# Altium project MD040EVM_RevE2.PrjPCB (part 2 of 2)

## Sheet MD040_ezFET_RevE2.SchDoc
size 431 x 279 mm; Date: Not shown in title block; ApprovedBy: Not shown in title block; CheckedBy: Not shown in title block; Author: Not shown in title block; CompanyName: Not shown in title block; Engineer: Not shown in title block; Organization: Not shown in title block; Address1: Not shown in title block; Address2: Not shown in title block; Address3: Not shown in title block; Address4: Not shown in title block; DocumentNumber: 2; Revision: Use project parameter SCH_Rev; SheetNumber: 2; SheetTotal: 3; PageSetup: Record=PageOptions¦CenterHorizontal=True¦CenterVertical=True¦PrintScale=1.00¦XCorrection=1.00¦YCorrection=1.00¦PrintKind=0¦BorderSize=5000000¦LeftOffset=0¦BottomOffset=0¦Orientation=2¦PaperLength=1000¦PaperWidth=1000¦Scale=100¦PaperSource=15¦PrintQuality=600¦MediaType=1¦DitherType=10¦PaperKind=Letter¦PrintScaleMode=1
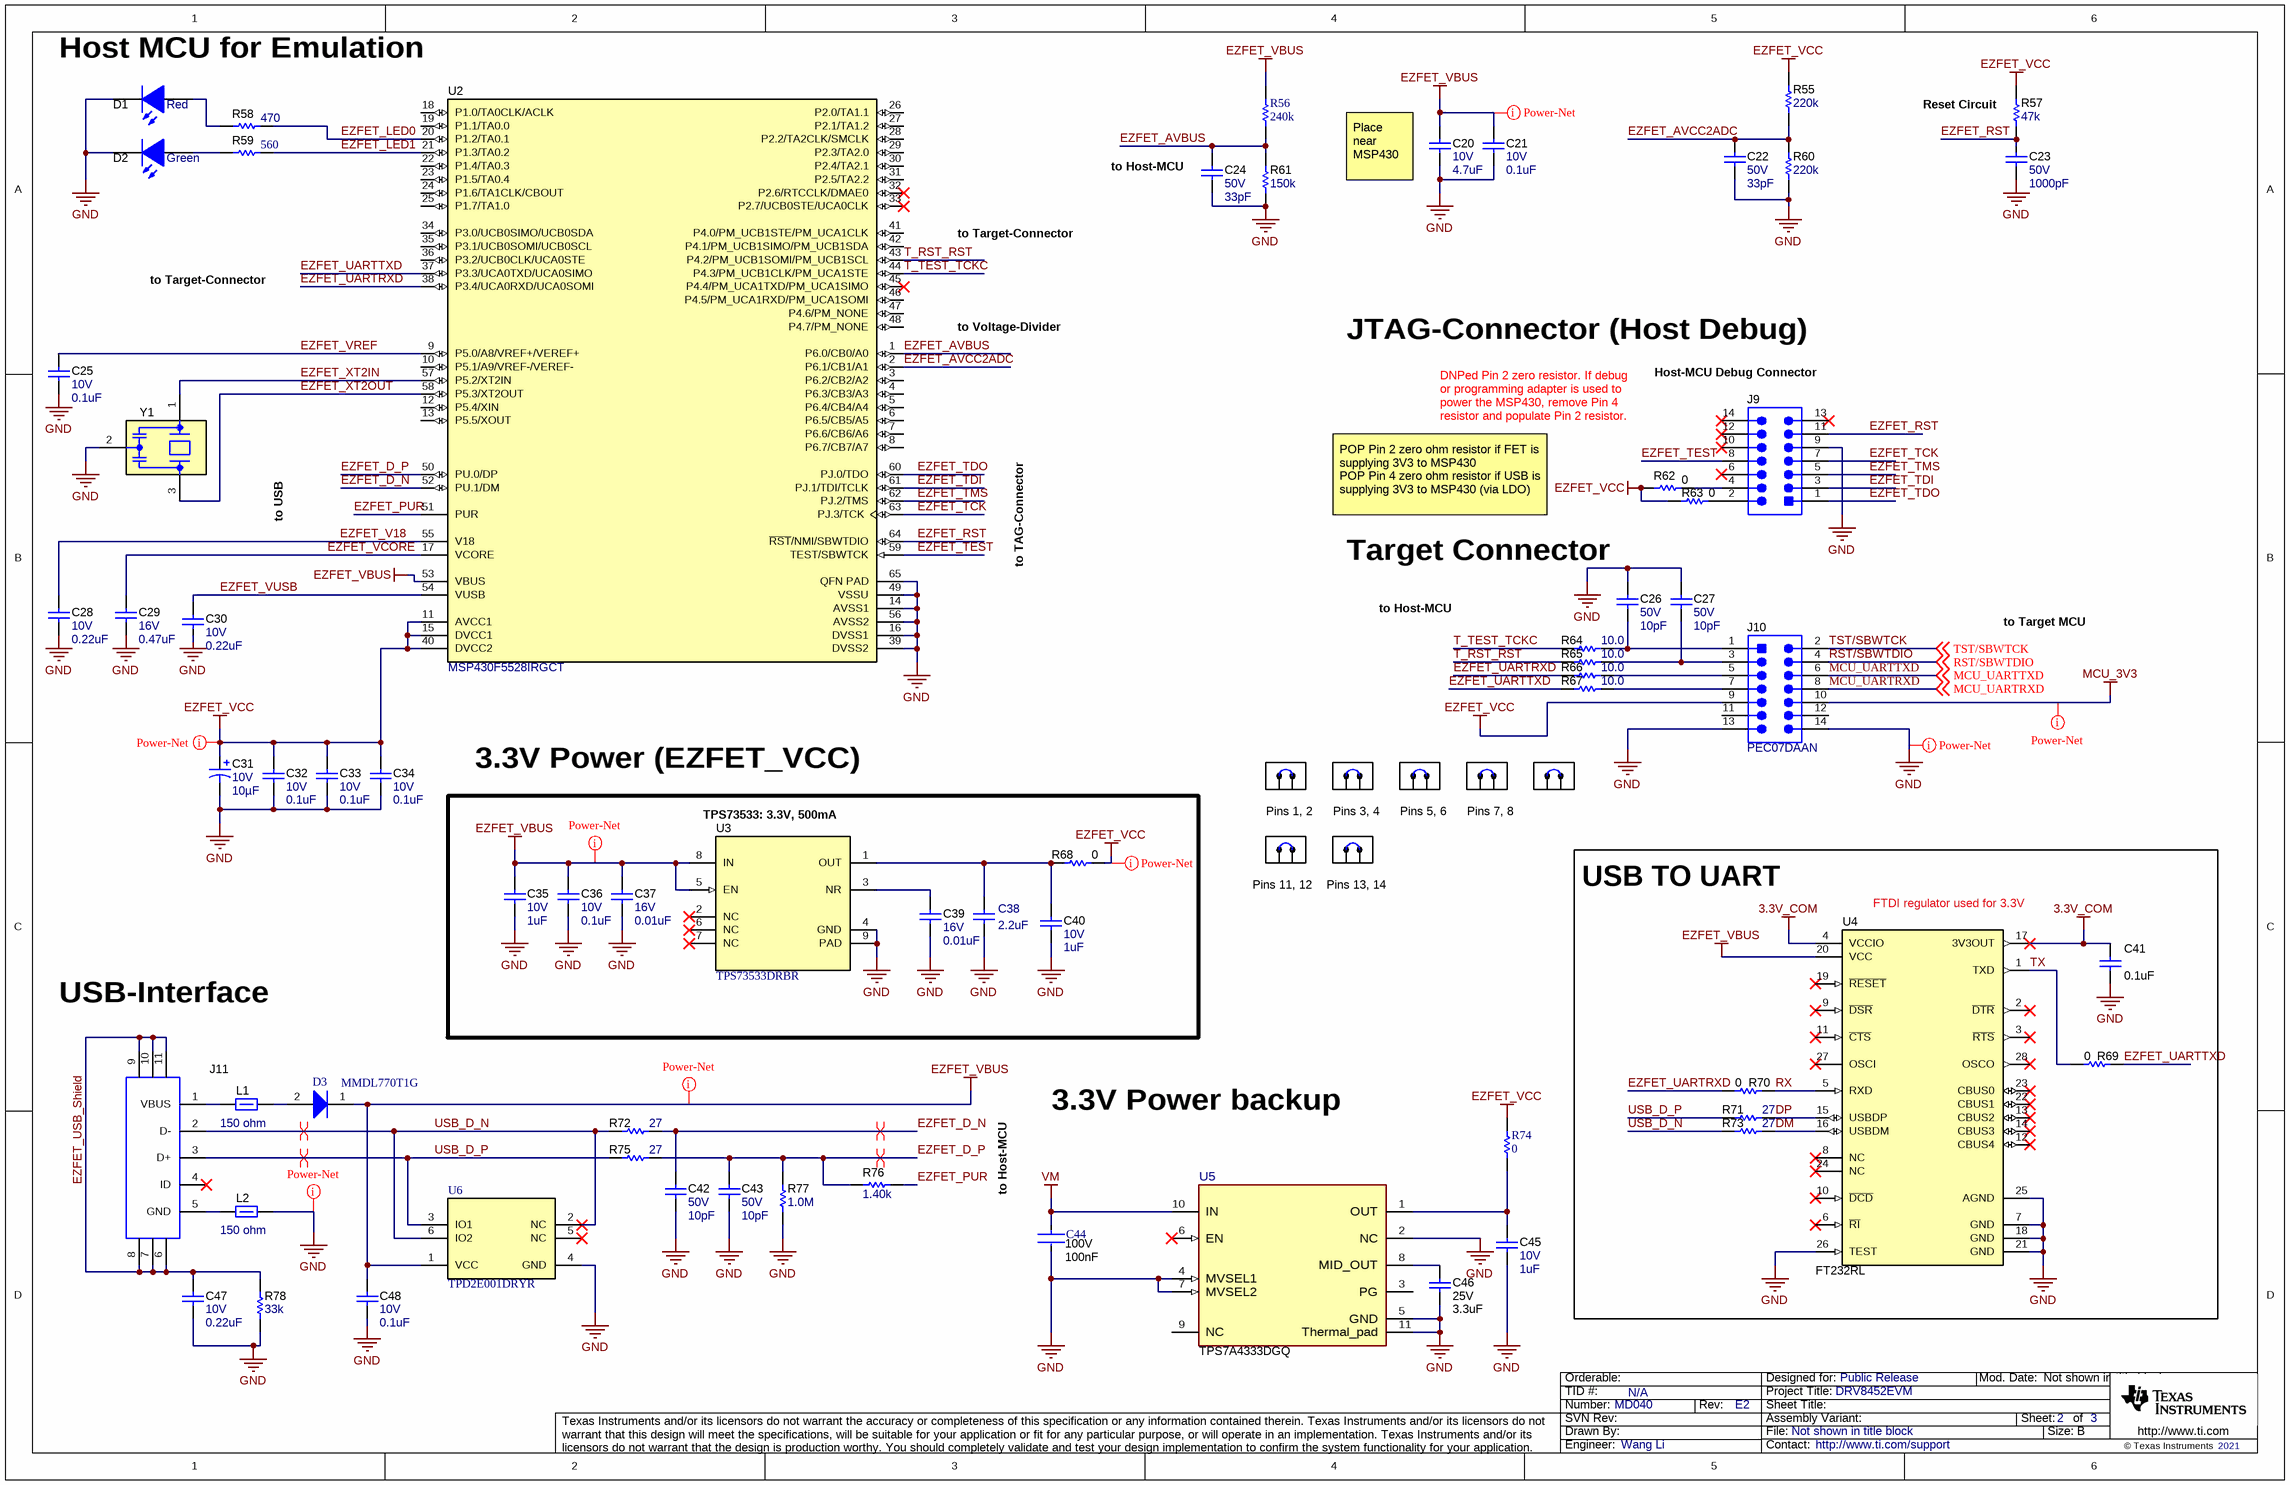
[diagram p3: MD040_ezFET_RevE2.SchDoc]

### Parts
C20  VDC_V: 10V  ValueDisplayed: 4.7uF  [0402]  (hidden comment: C1005X5R1A475M050BC)
C21  VDC_V: 10V  ValueDisplayed: 0.1uF  [0402]  (hidden comment: GRM155R61A104KA01D)
C22  VDC_V: 50V  ValueDisplayed: 33pF  [0402]  (hidden comment: C1005C0G1H330J050BA)
C23  VDC_V: 50V  ValueDisplayed: 1000pF  [0402]  (hidden comment: GRM155R71H102KA01D)
C24  VDC_V: 50V  ValueDisplayed: 33pF  [0402]  (hidden comment: C1005C0G1H330J050BA)
C25  VDC_V: 10V  ValueDisplayed: 0.1uF  [0402]  (hidden comment: GRM155R61A104KA01D)
C26  VDC_V: 50V  ValueDisplayed: 10pF  [0402]  (hidden comment: GRM1555C1H100FA01D)
C27  VDC_V: 50V  ValueDisplayed: 10pF  [0402]  (hidden comment: GRM1555C1H100FA01D)
C28  VDC_V: 10V  ValueDisplayed: 0.22uF  [0402]  (hidden comment: GRM155R61A224KE19D)
C29  VDC_V: 16V  ValueDisplayed: 0.47uF  [0402]  (hidden comment: GRM155R61C474KE01)
C30  VDC_V: 10V  ValueDisplayed: 0.22uF  [0402]  (hidden comment: GRM155R61A224KE19D)
C31  VDC_V: 10V  ValueDisplayed: 10µF  [3216-18]  (hidden comment: T520A106M010ATE080)
C32  VDC_V: 10V  ValueDisplayed: 0.1uF  [0402]  (hidden comment: GRM155R61A104KA01D)
C33  VDC_V: 10V  ValueDisplayed: 0.1uF  [0402]  (hidden comment: GRM155R61A104KA01D)
C34  VDC_V: 10V  ValueDisplayed: 0.1uF  [0402]  (hidden comment: GRM155R61A104KA01D)
C35  VDC_V: 10V  ValueDisplayed: 1uF  [0402]  (hidden comment: 885012105012)
C36  VDC_V: 10V  ValueDisplayed: 0.1uF  [0402]  (hidden comment: GRM155R61A104KA01D)
C37  VDC_V: 16V  ValueDisplayed: 0.01uF  [0402]  (hidden comment: GRM155R71C103KA01D)
C38  2.2uF  [0402]
C39  VDC_V: 16V  ValueDisplayed: 0.01uF  [0402]  (hidden comment: GRM155R71C103KA01D)
C40  VDC_V: 10V  ValueDisplayed: 1uF  [0402]  (hidden comment: 885012105012)
C41  ValueDisplayed: 0.1uF  [0402L]  (hidden comment: 885012105010)
C42  VDC_V: 50V  ValueDisplayed: 10pF  [0402]  (hidden comment: GRM1555C1H100FA01D)
C43  VDC_V: 50V  ValueDisplayed: 10pF  [0402]  (hidden comment: GRM1555C1H100FA01D)
C44  Voltage Rating: 100V  Capacitance: 100nF  [FP-0603-L_1_6_0_1-W_0_8_0-IPC_B]  (hidden comment: HMK107BJ104MA-T)
C45  VDC_V: 10V  ValueDisplayed: 1uF  [0402]  (hidden comment: 885012105012)
C46  VDC_V: 25V  ValueDisplayed: 3.3uF  [0805_HV]  (hidden comment: GRM21BC81E335KA73L)
C47  VDC_V: 10V  ValueDisplayed: 0.22uF  [0402]  (hidden comment: GRM155R61A224KE19D)
C48  VDC_V: 10V  ValueDisplayed: 0.1uF  [0402]  (hidden comment: GRM155R61A104KA01D)
D1  value Red  [WL-SMCW_RED]  (hidden comment: 150060RS75000)
D2  value Green  [WL-SMCW_GREEN]  (hidden comment: CMP-0002894-2)
D3  MMDL770T1G  [ONSC-SOD-323-2-477-02_V]
J9  61301421121  [Wurth_61301421121]  (value not drawn)
J10  PEC07DAAN  [CONN_PEC07DAAN]
J11  CMP-0055311-1  [Molex_1051640001]  (value not drawn)
L1  value 150 ohm  [0603]  (hidden comment: BLM18AG151BH1D)
L2  ValueDisplayed: 150 ohm  [0603]  (hidden comment: BLM18AG151BH1D)
R55  ValueDisplayed: 220k  [0402]  (hidden comment: RC0402FR-07220KL)
R56  240k  [RESC1005X40X25NL05T05]
R57  ValueDisplayed: 47k  [0402]  (hidden comment: CRCW040247K0JNED)
R58  ValueDisplayed: 470  [0402]  (hidden comment: CRCW0402470RJNED)
R59  ValueDisplayed: 560  [0402]  (hidden comment: CRCW0402560RJNED)
R60  ValueDisplayed: 220k  [0402]  (hidden comment: RC0402FR-07220KL)
R61  ValueDisplayed: 150k  [0402]  (hidden comment: CRCW0402150KFKED)
R62  value 0  [0402L]  (hidden comment: ERJ-2GE0R00X)
R63  value 0  [0402L]  (hidden comment: ERJ-2GE0R00X)
R64  ValueDisplayed: 10.0  [0402]  (hidden comment: CRCW040210R0FKED)
R65  ValueDisplayed: 10.0  [0402]  (hidden comment: CRCW040210R0FKED)
R66  ValueDisplayed: 10.0  [0402]  (hidden comment: CRCW040210R0FKED)
R67  ValueDisplayed: 10.0  [0402]  (hidden comment: CRCW040210R0FKED)
R68  value 0  [0402L]  (hidden comment: Resistor)
R69  value 0  [0603L]  (hidden comment: Resistor)
R70  value 0  [0603L]  (hidden comment: Resistor)
R71  ValueDisplayed: 27  [0402]  (hidden comment: CRCW040227R0JNED)
R72  ValueDisplayed: 27  [0402]  (hidden comment: CRCW040227R0JNED)
R73  ValueDisplayed: 27  [0402]  (hidden comment: CRCW040227R0JNED)
R74  0  [RESC1005X40X25NL05T05]
R75  ValueDisplayed: 27  [0402]  (hidden comment: CRCW040227R0JNED)
R76  ValueDisplayed: 1.40k  [0402]  (hidden comment: CRCW04021K40FKED)
R77  ValueDisplayed: 1.0M  [0402]  (hidden comment: CRCW04021M00JNED)
R78  ValueDisplayed: 33k  [0402]  (hidden comment: CRCW040233K0JNED)
SH-J23  60900213421  [Wurth_60900213421]  (value not drawn)
SH-J24  60900213421  [Wurth_60900213421]  (value not drawn)
SH-J25  60900213421  [Wurth_60900213421]  (value not drawn)
SH-J26  60900213421  [Wurth_60900213421]  (value not drawn)
SH-J27  60900213421  [Wurth_60900213421]  (value not drawn)
SH-J28  60900213421  [Wurth_60900213421]  (value not drawn)
SH-J29  60900213421  [Wurth_60900213421]  (value not drawn)
U2  PartNumber: MSP430F5528IRGCT  [RGC0064B]  (hidden comment: CMP-0039269-4)
U3  TPS73533DRBR  [DRB0008A]
U4  FT232RL  [SSOP28_N]
U5  TPS7A4333DGQ  [DGQ0010E-MFG]
U6  TPD2E001DRYR  [DRY0006A]
Y1  CSTNR4M00GH5L000R0  [MuRata_CSTNR]  (value not drawn)

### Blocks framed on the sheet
TPS73533: 3.3V, 500mA: C35-C40 R68 U3
USB TO UART: C41 R69-R71 R73 U4

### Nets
3.3V_COM: C41.1 U4.4(VCCIO) U4.17(3V3OUT)
EZFET_VBUS: C20.1 C21.1 C35.1 C36.1 C37.1 C48.1 D3.1(K) R56.2 U2.53(VBUS) U3.5(EN) U3.8(IN) U4.20(VCC) U6.1(VCC)
EZFET_VCC: C31.1(+) C32.1 C33.1 C34.1 J10.9 R55.2 R57.2 R62.1 R63.1 R68.2 R74.2 U2.11(AVCC1) U2.15(DVCC1) U2.40(DVCC2)
GND: C20.2 C21.2 C22.2 C23.2 C24.2 C25.2 C26.1 C27.1 C28.2 C29.2 C30.2 C31.2(-) C32.2 C33.2 C34.2 C35.2 C36.2 C37.2 C38.2 C39.2 C40.2 C41.2 C42.2 C43.2 C44.2 C45.2 C46.2 C47.2 C48.2 D1.1(K) D2.1(K) J9.9 J10.13 J10.14 L2.2 R60.1 R61.1 R77.1 R78.1 U2.14(AVSS1) U2.16(DVSS1) U2.39(DVSS2) U2.49(VSSU) U2.56(AVSS2) U2.65(QFN_PAD) U3.4(GND) U3.9(PAD) U4.7(GND) U4.18(GND) U4.21(GND) U4.25(AGND) U4.26(TEST) U5.2(NC) U5.4(MVSEL1) U5.5(GND) U5.7(MVSEL2) U5.11(Thermal_pad) U6.4(GND) Y1.2(GND)
MCU_3V3: J10.10
VM: C44.1 U5.10(IN)
DM: R73.2 U4.16(USBDM)
DP: R71.2 U4.15(USBDP)
EZFET_AVBUS: C24.1 R56.1 R61.2 U2.1(P6.0/CB0/A0)
EZFET_AVCC2ADC: C22.1 R55.1 R60.2 U2.2(P6.1/CB1/A1)
EZFET_D_N: C42.1 R72.2 U2.52(PU.1/DM)
EZFET_D_P: C43.1 R75.2 R76.1 R77.2 U2.50(PU.0/DP)
EZFET_LED0: R58.2 U2.20(P1.2/TA0.1)
EZFET_LED1: R59.2 U2.21(P1.3/TA0.2)
EZFET_PUR: R76.2 U2.51(PUR)
EZFET_RST: C23.1 J9.11 R57.1 U2.64(~{RST}/NMI/SBWTDIO)
EZFET_TCK: J9.7 U2.63(PJ.3/TCK)
EZFET_TDI: J9.3 U2.61(PJ.1/TDI/TCLK)
EZFET_TDO: J9.1 U2.60(PJ.0/TDO)
EZFET_TEST: J9.8 U2.59(TEST/SBWTCK)
EZFET_TMS: J9.5 U2.62(PJ.2/TMS)
EZFET_UARTRXD: R66.1 R70.2 U2.38(P3.4/UCA0RXD/UCA0SOMI)
EZFET_UARTTXD: R67.1 R69.1 U2.37(P3.3/UCA0TXD/UCA0SIMO)
EZFET_USB_Shield: C47.1 J11.6 J11.7 J11.8 J11.9 J11.10 J11.11 R78.2
EZFET_V18: C28.1 U2.55(V18)
EZFET_VCORE: C29.1 U2.17(VCORE)
EZFET_VREF: C25.1 U2.9(P5.0/A8/VREF+/VEREF+)
EZFET_VUSB: C30.1 U2.54(VUSB)
EZFET_XT2IN: U2.57(P5.2/XT2IN) Y1.1(In)
EZFET_XT2OUT: U2.58(P5.3/XT2OUT) Y1.3(Out)
MCU_UARTRXD: J10.8 ; off-sheet MCU_UARTRXD
MCU_UARTTXD: J10.6 ; off-sheet MCU_UARTTXD
RST/SBWTDIO: J10.4 ; off-sheet RST/SBWTDIO
RX: R70.1 U4.5(RXD)
T_RST_RST: R65.1 U2.43(P4.2/PM_UCB1SOMI/PM_UCB1SCL)
T_TEST_TCKC: R64.1 U2.44(P4.3/PM_UCB1CLK/PM_UCA1STE)
TST/SBWTCK: J10.2 ; off-sheet TST/SBWTCK
TX: R69.2 U4.1(TXD)
USB_D_N: J11.2(D-) R72.1 R73.1 U6.2(NC) U6.6(IO2)
USB_D_P: J11.3(D+) R71.1 R75.1 U6.3(IO1)
NetC26_2: C26.2 J10.1 R64.2
NetC27_2: C27.2 J10.3 R65.2
NetC38_1: C38.1 C40.1 R68.1 U3.1(OUT)
NetC39_1: C39.1 U3.3(NR)
NetC45_1: C45.1 R74.1 U5.1(OUT)
NetC46_1: C46.1 U5.8(MID_OUT)
NetD1_2: D1.2(A) R58.1
NetD2_2: D2.2(A) R59.1
NetD3_2: D3.2(A) L1.2
NetJ9_2: J9.2 R63.2
NetJ9_4: J9.4 R62.2
NetJ10_5: J10.5 R66.2
NetJ10_7: J10.7 R67.2
NetJ11_1: J11.1(VBUS) L1.1
NetJ11_5: J11.5(GND) L2.1

Not connected (* = marked no-connect by the designer): J9 6* 10* 12* 13* 14*; J10 11 12; J11 4(ID)*; U2 3(P6.2/CB2/A2) 4(P6.3/CB3/A3) 5(P6.4/CB4/A4) 6(P6.5/CB5/A5) 7(P6.6/CB6/A6) 8(P6.7/CB7/A7) 10(P5.1/A9/VREF-/VEREF-) 12(P5.4/XIN) 13(P5.5/XOUT) 18(P1.0/TA0CLK/ACLK) 19(P1.1/TA0.0) 22(P1.4/TA0.3) 23(P1.5/TA0.4) 24(P1.6/TA1CLK/CBOUT) 25(P1.7/TA1.0) 26(P2.0/TA1.1) 27(P2.1/TA1.2) 28(P2.2/TA2CLK/SMCLK) 29(P2.3/TA2.0) 30(P2.4/TA2.1) 31(P2.5/TA2.2) 32(P2.6/RTCCLK/DMAE0)* 33(P2.7/UCB0STE/UCA0CLK)* 34(P3.0/UCB0SIMO/UCB0SDA) 35(P3.1/UCB0SOMI/UCB0SCL) 36(P3.2/UCB0CLK/UCA0STE) 41(P4.0/PM_UCB1STE/PM_UCA1CLK) 42(P4.1/PM_UCB1SIMO/PM_UCB1SDA) 45(P4.4/PM_UCA1TXD/PM_UCA1SIMO)* 46(P4.5/PM_UCA1RXD/PM_UCA1SOMI) 47(P4.6/PM_NONE) 48(P4.7/PM_NONE); U3 2(NC)* 6(NC)* 7(NC)*; U4 2(~{DTR})* 3(~{RTS})* 6(~{RI})* 8(NC)* 9(~{DSR})* 10(~{DCD})* 11(~{CTS})* 12(CBUS4)* 13(CBUS2)* 14(CBUS3)* 19(~{RESET})* 22(CBUS1)* 23(CBUS0)* 24(NC)* 27(OSCI)* 28(OSCO)*; U5 3(PG) 6(EN)* 9(NC); U6 5(NC)*

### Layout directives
net class Power-Net: EZFET_VBUS, EZFET_VCC, GND, MCU_3V3
differential pair: EZFET_D_N, EZFET_D_P, USB_D_N, USB_D_P

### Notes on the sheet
- (near D1) Host MCU for Emulation
- (near C24) to Host-MCU
- (near R57) Reset Circuit
- to Target-Connector
- (near C20) Place near MSP430
- to Voltage-Divider
- JTAG-Connector (Host Debug)
- DNPed Pin 2 zero resistor. If debug or programming adapter is used to power the MSP430, remove Pin 4 resistor and populate Pin 2 resistor.
- (near J9) Host-MCU Debug Connector
- to USB
- to TAG-Connector
- POP Pin 2 zero ohm resistor if FET is supplying 3V3 to MSP430
  POP Pin 4 zero ohm resistor if USB is supplying 3V3 to MSP430 (via LDO)
- Target Connector
- to Host-MCU
- to Target MCU
- 3.3V Power (EZFET_VCC)
- Pins 1, 2
- Pins 3, 4
- (near SH-J25) Pins 5, 6
- (near SH-J26) Pins 7, 8
- (near SH-J28) Pins 11, 12
- Pins 13, 14
- (near U4) FTDI regulator used for 3.3V
- USB-Interface
- 3.3V Power backup

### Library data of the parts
C20 = CMP-0006269-2: CAP, CERM, 4.7 uF, 10 V, +/- 20%, X5R, 0402; Manufacturer: TDK; TaMin_C: -55°C; Polarized: N; SizeAreaWB_mm2: 3; Value1: Unknown; U/M: EA; Value: 4.7uF; TaMax_C: 85°C; SizeZ_mm: 0.6; SizeX_mm: 1; SizeY_mm: 0.5; Cap_F: 4.7µF; AEC Category: Q200
C21 C25 C32-C34 C36 C48 = CMP-0006562-2: CAP, CERM, 0.1 uF, 10 V, +/- 10%, X5R, 0402; Manufacturer: MuRata; TaMin_C: -55°C; Polarized: N; SizeAreaWB_mm2: 3; Value1: Unknown; U/M: EA; Value: 0.1uF; TaMax_C: 85°C; SizeZ_mm: 0.6; SizeX_mm: 1; SizeY_mm: 0.5; Cap_F: 100nF; AEC Category: Q200
C22 C24 = CMP-0006250-2: CAP, CERM, 33 pF, 50 V, +/- 5%, C0G/NP0, 0402; Manufacturer: TDK; TaMin_C: -55°C; Polarized: N; SizeAreaWB_mm2: 3; Value1: Unknown; U/M: EA; Value: 33pF; TaMax_C: 125°C; SizeZ_mm: 0.6; SizeX_mm: 1; SizeY_mm: 0.5; AEC Category: Q200
C23 = CMP-0006673-2: CAP, CERM, 1000 pF, 50 V, +/- 10%, X7R, 0402; Manufacturer: MuRata; TaMin_C: -55°C; Polarized: N; SizeAreaWB_mm2: 3; Value1: Unknown; U/M: EA; Value: 1000pF; TaMax_C: 125°C; SizeZ_mm: 0.6; SizeX_mm: 1; SizeY_mm: 0.5; Cap_F: 1nF; AEC Category: Q200
C26 C27 C42 C43 = CMP-0064916-2: CAP, CERM, 10 pF, 50 V,+/- 1%, C0G/NP0, 0402; Manufacturer: MuRata; TaMin_C: -55°C; Polarized: N; SizeAreaWB_mm2: 3; Value1: Unknown; U/M: EA; Value: 10pF; TaMax_C: 125°C; SizeZ_mm: 0.6; SizeX_mm: 1; SizeY_mm: 0.5; AEC Category: Q200
C28 C30 C47 = CMP-0006570-2: CAP, CERM, 0.22 uF, 10 V, +/- 10%, X5R, 0402; Manufacturer: MuRata; TaMin_C: -55°C; Polarized: N; SizeAreaWB_mm2: 3; Value1: Unknown; U/M: EA; Value: 0.22uF; TaMax_C: 85°C; SizeZ_mm: 0.6; SizeX_mm: 1; SizeY_mm: 0.5; Cap_F: 220nF; AEC Category: Q200
C29 = CMP-0006600-2: CAP, CERM, 0.47 uF, 16 V, +/- 10%, X5R, 0402; Manufacturer: MuRata; TaMin_C: -55°C; Polarized: N; SizeAreaWB_mm2: 3; Value1: Unknown; U/M: EA; Value: 0.47uF; TaMax_C: 85°C; SizeZ_mm: 0.6; SizeX_mm: 1; SizeY_mm: 0.5; Cap_F: 470nF; AEC Category: Q200
C31 = CMP-0084376-1: CAP, Tantalum Polymer, 10 µF, 10 V,+/- 20%, 0.08 ohm, 3216-18 SMD; Manufacturer: Kemet; TaMin_C: -55°C; SizeArea_mm2: 5.12; Value: 10uF; SizeAreaWB_mm2: 10.92; SizeY_mm: 1.6; Polarized: Y; SizeX_mm: 3.2; AEC Qualified: N; TaMax_C: 105°C; SizeZ_mm: 1.8; ESR_ohm: 0.08; CompType: Capacitor; AEC Category: Q200
C35 C40 C45 = CMP-0064924-2: CAP, CERM, 1 uF, 10 V,+/- 20%, X5R, 0402; Manufacturer: Wurth Elektronik; TaMin_C: -55°C; Polarized: N; SizeAreaWB_mm2: 3; Value1: Unknown; U/M: EA; Value: 1uF; TaMax_C: 85°C; SizeZ_mm: 0.6; SizeX_mm: 1; SizeY_mm: 0.5; Cap_F: 1µF; AEC Category: Q200
C37 C39 = CMP-0006639-2: CAP, CERM, 0.01 uF, 16 V, +/- 10%, X7R, 0402; Manufacturer: MuRata; TaMin_C: -55°C; Polarized: N; SizeAreaWB_mm2: 3; Value1: Unknown; U/M: EA; Value: 0.01uF; TaMax_C: 125°C; SizeZ_mm: 0.6; SizeX_mm: 1; SizeY_mm: 0.5; Cap_F: 10nF; AEC Category: Q200
C38 = CMP-0006594-2: CAP, CERM, 2.2 uF, 16 V, +/- 10%, X5R, 0402; Manufacturer: MuRata; PartNumber: GRM155R61C225KE11D; TaMin_C: -55°C; Polarized: N; SizeAreaWB_mm2: 3; Value1: Unknown; U/M: EA; TaMax_C: 85°C; SizeZ_mm: 0.6; SizeX_mm: 1; SizeY_mm: 0.5; Value2: 16V; CompType: Capacitor; Cap_F: 2.2µF; AEC Category: Q200
C41 = CMP-0006221-1: CAP, CERM, 0.1 uF, 10 V, +/- 20%, X5R, 0402; Manufacturer: Wurth Elektronik; Value: 0.1uF; Polarized: N; U/M: EA; Cap_F: 100nF; Value1: Unknown; VDC_V: 10V; TaMin_C: -55°C; TaMax_C: 85°C; Cap_Case: 0402; AEC Category: Q200; SizeArea_mm2: 0.5; SizeAreaWB_mm2: 3; SizeX_mm: 1; SizeZ_mm: 0.6
C44 = CMP-14477-003474-1: Ceramic Capacitor General Use 0.1uF ±20% 100V X5R 0603
C46 = CMP-0008271-1: CAP, CERM, 3.3 uF, 25 V, +/- 10%, X6S, 0805; Manufacturer: MuRata; TaMin_C: -55°C; Polarized: N; SizeAreaWB_mm2: 6.75; Value1: Unknown; U/M: EA; Value: 3.3uF; TaMax_C: 105°C; SizeZ_mm: 1.45; SizeX_mm: 2; SizeY_mm: 1.25; Cap_Case: 0805; SizeArea_mm2: 2.5; Cap_F: 3.3µF; AEC Category: Q200
D1 = CMP-0002947-3: LED, Red, SMD; Manufacturer: Wurth Elektronik; Type: AlInGaP; Vf_V: 2V; Io_A: 30mA; Vr_V: 5V; Tjmax_C: 85°C; Power_TotalModule: 72mW; Value1: 0.072W; Angle: 140
D2 = CMP-0002894-2: LED, Green, SMD; Manufacturer: Wurth Elektronik; PartNumber: 150060VS75000; Type: AlInGaP; Vf_V: 2V; Io_A: 20mA; Value1: W
D3 = CMP-1055-00457-1: Schottky Barrier Diode, 2-Pin SOD-323, Pb-Free, Tape and Reel; Manufacturer: On Semiconductor; Configuration: Single
J9 = CMP-0086014-1: Header, 2.54mm, 7x2, Gold, TH; Manufacturer: Wurth Elektronik; Pitch_mm: 2.54; Voltage_V: 250V; Shrouded: N; Gender: Male; Current_A: 3A; Cert_UL: Y; Row_Count: 2
J10 = CMP-0002339-2: Header, 100mil, 7x2, Tin, TH; Manufacturer: Sullins Connector Solutions; Current_A: 3A; Green_Lifecycle: Active; Shrouded: N; Gender: Male; Green_REACh: Passed; Voltage_V: 1.8kV; Row_Count: 2; RowSpacing_mm: 2.54; Cert_UL: Y
J11 = CMP-0055311-1: Receptacle, USB 2.0, Micro B, 5 Position, R/A, SMT; PartNumber: 1051640001; Manufacturer: Molex; Pitch_mm: 0.65; Gender: Female; ContactFinish: Gold; Current_A: 1.8A; Voltage_V: 30V; Cert_UL: Y; CNHeader: FALSE; CT: TRUE
L1 = CMP-0081962-1: Ferrite Bead, 150 ohm @ 100 MHz, 0.7 A, 0603; Manufacturer: MuRata; SizeAreaWB_mm2: 4.68; SizeArea_mm2: 1.28; SizeZ_mm: 1; Imax_A: 700mA; ZTyp@100MHz_Ohm: 150; SizeY_mm: 0.8; Value2: 0.7A; Value1: 0.35 ohm; DCR_ohm: 0.35; SizeX_mm: 1.6
L2 = CMP-0081962-1: Ferrite Bead, 150 ohm @ 100 MHz, 0.7 A, 0603; Manufacturer: MuRata; SizeAreaWB_mm2: 4.68; SizeArea_mm2: 1.28; Value: 150 ohm; SizeZ_mm: 1; Imax_A: 700mA; ZTyp@100MHz_Ohm: 150; SizeY_mm: 0.8; Value2: 0.7A; Value1: 0.35 ohm; DCR_ohm: 0.35; SizeX_mm: 1.6
R55 R60 = CMP-0026728-1: RES, 220 k, 1%, 0.0625 W, 0402; Manufacturer: Yageo America; Power_W: 62.5mW; TempCo: 100 ppm/C; U/M: EA; Value: 220k; SizeX_mm: 1; SizeY_mm: 0.5; SizeZ_mm: 0.6; AEC Qualified: N; VDC_V: 50V; AEC Category: Q200
R56 = CMP-2002-00799-3: Chip Resistor, 240 KOhm, +/- 1%, 100 mW, -55 to 155 degC, 0402 (1005 Metric), RoHS, Tape and Reel; Manufacturer: Basic Passives; PartNumber: ERJ-2RKF2403X; Power Rating: 100 mW; Voltage Rating: 50 V; Case\/Package: 0402
R57 = CMP-0026935-3: RES, 47 k, 5%, 0.063 W, AEC-Q200 Grade 0, 0402; Manufacturer: Vishay-Dale; Power_W: 63mW; TempCo: 200 ppm/C; Value_Code: 47k0; Value: 47k; EIA_Code: E24; SizeX_mm: 1; SizeY_mm: 0.5; SizeZ_mm: 0.6; Value2: 0.063W; AEC Qualified: Y; VDC_V: 50V; AEC Category: Q200; AEC Grade: 0
R58 = CMP-0026934-3: RES, 470, 5%, 0.063 W, AEC-Q200 Grade 0, 0402; Manufacturer: Vishay-Dale; Value: 470; Value_Code: 470R; Power_W: 63mW; Value2: 0.063W; VDC_V: 50V; TempCo: 200 ppm/C; SizeArea_mm2: 0.5; SizeX_mm: 1; SizeZ_mm: 0.6; EIA_Code: E24; AEC Category: Q200; AEC Qualified: Y; AEC Grade: 0
R59 = CMP-0026948-3: RES, 560, 5%, 0.063 W, AEC-Q200 Grade 0, 0402; Manufacturer: Vishay-Dale; Power_W: 63mW; TempCo: 200 ppm/C; Value_Code: 560R; Value: 560; EIA_Code: E24; SizeX_mm: 1; SizeY_mm: 0.5; SizeZ_mm: 0.6; Value2: 0.063W; AEC Qualified: Y; VDC_V: 50V; AEC Category: Q200; AEC Grade: 0
R61 = CMP-0026021-3: RES, 150 k, 1%, 0.063 W, AEC-Q200 Grade 0, 0402; Manufacturer: Vishay-Dale; Power_W: 63mW; TempCo: 100 ppm/C; Value: 150k; EIA_Code: E96; SizeX_mm: 1; SizeY_mm: 0.5; SizeZ_mm: 0.6; Value2: 0.063W; AEC Qualified: Y; VDC_V: 50V; AEC Category: Q200; AEC Grade: 0
R62 R63 = CMP-0026992-3: RES, 0, 5%, 0.1 W, AEC-Q200 Grade 0, 0402; Manufacturer: Panasonic; Value_Code: 0000; Power_W: 100mW; Value2: 0.1W; VDC_V: 50V; TempCo: 600 ppm/C; EIA_Code: E24; AEC Category: Q200; AEC Qualified: Y; SizeArea_mm2: 0.5; SizeAreaWB_mm2: 3; SizeX_mm: 1; SizeZ_mm: 0.6
R64-R67 = CMP-0025963-2: RES, 10.0, 1%, 0.063 W, 0402; Manufacturer: Vishay-Dale; Power_W: 63mW; TempCo: 100 ppm/C; Value_Code: 10R0; U/M: EA; Value: 10.0; EIA_Code: E96; Res_ohm: 10; SizeX_mm: 1; SizeY_mm: 0.5; SizeZ_mm: 0.6; Value2: 0.063W; VDC_V: 50V; AEC Category: Q200
R68 = CMP-0026992-3: RES, 0, 5%, 0.1 W, AEC-Q200 Grade 0, 0402; Manufacturer: Panasonic; PartNumber: ERJ-2GE0R00X; Value_Code: 0000; Power_W: 100mW; Value2: 0.1W; VDC_V: 50V; TempCo: 600 ppm/C; EIA_Code: E24; AEC Category: Q200; AEC Qualified: Y; SizeArea_mm2: 0.5; SizeAreaWB_mm2: 3; SizeX_mm: 1; SizeZ_mm: 0.6
R69 R70 = CMP-0025697-4: RES, 0, 5%, 0.1 W, AEC-Q200 Grade 0, 0603; PartNumber: CRCW06030000Z0EA; Manufacturer: Vishay-Dale; Value_Code: 0000; Power_W: 100mW; Value2: 0.1W; VDC_V: 75V; TempCo: 200 ppm/C; EIA_Code: E24; AEC Category: Q200; AEC Qualified: Y; SizeArea_mm2: 1.28; SizeX_mm: 1.6; SizeY_mm: 0.8; SizeZ_mm: 1
R71-R73 R75 = CMP-0026888-3: RES, 27, 5%, 0.063 W, AEC-Q200 Grade 0, 0402; Manufacturer: Vishay-Dale; Power_W: 63mW; TempCo: 200 ppm/C; Value_Code: 27R0; Value: 27; EIA_Code: E24; SizeX_mm: 1; SizeY_mm: 0.5; SizeZ_mm: 0.6; Value2: 0.063W; AEC Qualified: Y; VDC_V: 50V; AEC Category: Q200; AEC Grade: 0
R74 = CMP-2002-00429-1: Manufacturer: Panasonic; Part Number: ERJ-2GE0R00X
R76 = CMP-0026085-3: RES, 1.40 k, 1%, 0.063 W, AEC-Q200 Grade 0, 0402; Manufacturer: Vishay-Dale; Power_W: 63mW; TempCo: 100 ppm/C; Value_Code: 1k40; Value: 1.40k; EIA_Code: E96; Res_ohm: 1.4k; SizeX_mm: 1; SizeY_mm: 0.5; SizeZ_mm: 0.6; Value2: 0.063W; AEC Qualified: Y; VDC_V: 50V; AEC Category: Q200; AEC Grade: 0
R77 = CMP-0026859-2: RES, 1.0 M, 5%, 0.063 W, AEC-Q200 Grade 0, 0402; Manufacturer: Vishay-Dale; Power_W: 63mW; TempCo: 200 ppm/C; Value_Code: 1M00; Value: 1.0Meg; EIA_Code: E24; Res_ohm: 1M; SizeX_mm: 1; SizeY_mm: 0.5; SizeZ_mm: 0.6; Value2: 0.063W; AEC Qualified: Y; VDC_V: 50V; AEC Category: Q200; AEC Grade: 0
R78 = CMP-0026907-3: RES, 33 k, 5%, 0.063 W, AEC-Q200 Grade 0, 0402; Manufacturer: Vishay-Dale; Power_W: 63mW; TempCo: 200 ppm/C; Value_Code: 33k0; Value: 33k; EIA_Code: E24; SizeX_mm: 1; SizeY_mm: 0.5; SizeZ_mm: 0.6; Value2: 0.063W; AEC Qualified: Y; VDC_V: 50V; AEC Category: Q200; AEC Grade: 0
SH-J23-SH-J29 = CMP-0003761-2: Shunt, 2.54mm, Gold, Black; Manufacturer: Wurth Elektronik
U2 = CMP-0039269-4: 16-Bit Ultra-Low-Power Microcontroller, 128KB Flash, 8KB RAM, USB, 12Bit ADC, 2 USCIs, 32Bit HW MPY, RGC0064B (VQFN-64); Alternate Manufacturer: Texas Instruments; Alternate PartNumber: MSP430F5528IRGCR; ADC: 12-bit SAR; ADC Channels: 16; Brown Out Reset: Yes; DMA: 3; Flash(KB): 128; Frequency(MHz): 25; GPIO: 47; Multiplier: 32x32; SRAM(B): 8192; Timers - 16-bit: 4; USB: 1; USCI_A (UART/LIN/IrDA/SPI): 2; Rating: Catalog; SizeArea_mm2: 81.0; SizeZ_mm: 1.0; Green_REACh: Passed; AEC Qualified: N; AEC Category: Q200; CompType: IC; Green_Lifecycle: Active; SizeY_mm: 9.0; SizeAreaWB_mm2: 121.0
U3 = CMP-0036328-3: 500mA, Adjustable, Low Quiescent Current, Low-Noise, High-PSRR, Single-Output LDO Regulator, DRB0008A (VSON-8); Manufacturer: Texas Instruments; CompType: IC; Green_Lifecycle: Active; SizeZ_mm: 1.0; Iq(Typ)(mA): 0.04; SizeY_mm: 3.0; SizeAreaWB_mm2: 16.0; SizeArea_mm2: 9.0; AEC Category: Q200; Vout Adj(Max)(V): 3.3; AEC Qualified: N; Accuracy(%): 2; Vin(Max)(V): 6.5; Vdo(Typ)(mV): 280; Iout(Max)(A): 0.5; Green_REACh: Passed; Rating: Catalog; Vin(Min)(V): 2.7
U4 = CMP-0004774-1: USB to Serial UART, SSOP28; Manufacturer: FTDI
U5 = CMP-0090815-1: LDO, Fixed Output, Dual, 3.3V, 10/12/15V, 50mA, Precision Enable, Power-Good, HVSSOP10; Manufacturer: Texas Instruments; Output Type: Fixed,Multi; Max Supply Voltage: 85V; TJmax_C: +125°C; Output Voltage: 3.3/10/12/15V; SizeZ_mm: 1.1mm; Dropout Voltage: 200/800mV; Min Supply Voltage: 4V; Standoff Height: 0.05mm; AEC Qualified: No; Number Of Outputs: 2; Accuracy Percentage: 1%; Nominal Supply Current: 100uA
U6 = CMP-0043099-3: Low-Capacitance 2-Channel +/-15kV ESD Protection Array for High-Speed Data Interfaces, DRY0006A (USON-6); Manufacturer: Texas Instruments; IO Leakage Current(nA): 1; IEC 61000-4-2 Air-Gap(+/- kV): 15; USB High Speed: TRUE; IO Capacitance(Typ)(pF): 1.5; Eco-Plan: Green (RoHS & no Sb/Br); Breakdown Voltage(Min)(V): 11; IEC 61000-4-2 Contact(+/- kV): 8; AEC Category: Q200; AEC Qualified: N; CompType: IC; SizeAreaWB_mm2: 4.9; SizeArea_mm2: 1.45; SizeX_mm: 1.0; SizeZ_mm: 0.6; Rating: Catalog
Y1 = CMP-0085483-1: Oscillator, 4 MHz, 700 ppm, 39 pF, SMD; Manufacturer: MuRata; SizeArea_mm2: 9; Load Capacitance: 39 pF; SizeZ_mm: 1.2; AEC Category: Q200; Frequency Tolerance: 700 ppm; SizeX_mm: 4.5; SizeAreaWB_mm2: 16.5; TaMax_C: 85°C; TaMin_C: -20°C; SizeY_mm: 2; AEC Qualified: N; Frequency_Fixed: 4MHz

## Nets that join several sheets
GND: MD040_Motor_control_RevE2 (38 pins), MD040_Motor_Driver_RevE2 (55 pins), MD040_ezFET_RevE2 (59 pins)
MCU_3V3: MD040_Motor_control_RevE2 (17 pins), MD040_Motor_Driver_RevE2 (11 pins), MD040_ezFET_RevE2 (J10.10)
VM: MD040_Motor_Driver_RevE2 (18 pins), MD040_ezFET_RevE2 (C44.1 U5.10)
ACCEL/DECEL: MD040_Motor_control_RevE2 (U1.37), MD040_Motor_Driver_RevE2 (D10.2)
DIR/IN2: MD040_Motor_control_RevE2 (J8.12 R32.1), MD040_Motor_Driver_RevE2 (U7.40)
DRV_ENABLE: MD040_Motor_control_RevE2 (U1.36), MD040_Motor_Driver_RevE2 (D9.2)
ENABLE/IN1: MD040_Motor_control_RevE2 (J8.14 R33.1), MD040_Motor_Driver_RevE2 (U7.41)
EVM_STATUS: MD040_Motor_control_RevE2 (U1.34), MD040_Motor_Driver_RevE2 (D6.2)
FAULT: MD040_Motor_control_RevE2 (U1.40), MD040_Motor_Driver_RevE2 (D12.2)
GUI_STATUS: MD040_Motor_control_RevE2 (U1.35), MD040_Motor_Driver_RevE2 (D8.2)
ID1: MD040_Motor_control_RevE2 (U1.33), MD040_Motor_Driver_RevE2 (R99.2 R105.1)
ID2: MD040_Motor_control_RevE2 (U1.32), MD040_Motor_Driver_RevE2 (R100.2 R106.1)
ID3: MD040_Motor_control_RevE2 (U1.31), MD040_Motor_Driver_RevE2 (R101.2 R107.1)
ID4: MD040_Motor_control_RevE2 (U1.84), MD040_Motor_Driver_RevE2 (R102.2 R108.1)
ID5: MD040_Motor_control_RevE2 (U1.85), MD040_Motor_Driver_RevE2 (R103.2 R109.1)
INDEXER HOME: MD040_Motor_control_RevE2 (U1.39), MD040_Motor_Driver_RevE2 (D11.2)
MCU_UARTRXD: MD040_Motor_control_RevE2 (U1.61), MD040_ezFET_RevE2 (J10.8)
MCU_UARTTXD: MD040_Motor_control_RevE2 (U1.60), MD040_ezFET_RevE2 (J10.6)
MODE2/IPROPI4: MD040_Motor_control_RevE2 (J4.8 R14.1), MD040_Motor_Driver_RevE2 (J16.2 R79.2 U7.29)
MODE/MODE1: MD040_Motor_control_RevE2 (J4.6 R11.1), MD040_Motor_Driver_RevE2 (U7.28)
nFAULT: MD040_Motor_control_RevE2 (J4.2 R6.1), MD040_Motor_Driver_RevE2 (R83.1 R112.1 U7.26)
nHOME/OCPM: MD040_Motor_control_RevE2 (J4.4 R9.1), MD040_Motor_Driver_RevE2 (R88.1 U7.27)
nSCS/M0/EN4/VREF1/VREF: MD040_Motor_control_RevE2 (J25.1 J26.1 R23.1), MD040_Motor_Driver_RevE2 (U7.34)
nSLEEP: MD040_Motor_control_RevE2 (J8.16 R34.1), MD040_Motor_Driver_RevE2 (U7.42)
RST/SBWTDIO: MD040_Motor_control_RevE2 (C74.1 J3.11 R29.2 U1.96), MD040_Motor_Driver_RevE2 (J27.1), MD040_ezFET_RevE2 (J10.4)
RSVD/IPROPI1/IPROPI2/IPROPI: MD040_Motor_control_RevE2 (J4.14 R21.1), MD040_Motor_Driver_RevE2 (J17.2 R80.2 U7.32)
RSVD/IPROPI2/IPROPI1/IPROPI: MD040_Motor_control_RevE2 (J4.12 R18.1), MD040_Motor_Driver_RevE2 (J18.2 J19.2 R81.2 U7.31)
RSVD/IPROPI3: MD040_Motor_control_RevE2 (J4.10 R17.1), MD040_Motor_Driver_RevE2 (J19.1 J20.2 R82.2 U7.30)
RSVD/TOFF/EN3: MD040_Motor_control_RevE2 (J8.2 R24.1), MD040_Motor_Driver_RevE2 (U7.35)
SCLK/M1/IN4/RSVD: MD040_Motor_control_RevE2 (J8.8 R27.1), MD040_Motor_Driver_RevE2 (U7.38)
SDI/DECAY0/EN1/DECAY: MD040_Motor_control_RevE2 (J8.6 R26.1), MD040_Motor_Driver_RevE2 (U7.37)
SDO/DECAY1/EN2/RSVD: MD040_Motor_control_RevE2 (J8.4 R25.1), MD040_Motor_Driver_RevE2 (U7.36)
STEP/IN3/RSVD: MD040_Motor_control_RevE2 (J8.10 R30.1), MD040_Motor_Driver_RevE2 (U7.39)
TST/SBWTCK: MD040_Motor_control_RevE2 (J3.8 U1.91), MD040_ezFET_RevE2 (J10.2)
VREF/VREF2: MD040_Motor_control_RevE2 (J5.1 J6.1 J7.1 J25.2), MD040_Motor_Driver_RevE2 (U7.33)
VSEN_AOUT1: MD040_Motor_control_RevE2 (R5.1 R7.1), MD040_Motor_Driver_RevE2 (C67.1 R89.1 R93.2)
VSEN_AOUT2: MD040_Motor_control_RevE2 (R8.1 R10.1), MD040_Motor_Driver_RevE2 (C68.1 R90.1 R94.2)
VSEN_BOUT1: MD040_Motor_control_RevE2 (R12.1 R13.1), MD040_Motor_Driver_RevE2 (C69.1 R91.1 R95.2)
VSEN_BOUT2: MD040_Motor_control_RevE2 (R15.1 R16.1), MD040_Motor_Driver_RevE2 (C70.1 R92.1 R96.2)
VSEN_VM: MD040_Motor_control_RevE2 (J1.3 TP37.1 U1.1), MD040_Motor_Driver_RevE2 (C71.1 R98.1 R104.2)

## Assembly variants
001: not fitted A1 A2 A4 C1 C2 C3 C4 C5 C6 C41 C44 C45 C46 C72 C73 J1 J2 J3 J22 J24 R1 R6 R7 R9 R10 R11 R12 R14 R15 R17 R18 R21 R22 R23 R24 R25 R26 R27 R30 R32 R33 R34 R54 R63 R69 R70 R71 R73 R74 R101 R103 R105 R106 R108 TP13 TP15 TP16 TP37 TP38 TP39 TP40 TP41 TP42 TP43 TP44 TP45 TP46 U4 U5 Y2
002: not fitted A1 A2 A4 C1 C2 C3 C4 C5 C6 C41 C44 C45 C46 C72 C73 J1 J2 J3 J16 J17 J18 J19 J20 J22 J24 R1 R6 R7 R9 R10 R11 R12 R14 R15 R17 R18 R21 R22 R23 R24 R25 R26 R27 R30 R32 R33 R34 R54 R69 R70 R71 R73 R74 R79 R80 R81 R82 R84 R85 R86 R87 R88 R102 R103 R105 R106 R107 TP13 TP15 TP16 TP37 TP38 TP39 TP40 TP41 TP42 TP43 TP44 TP45 TP46 U4 U5 Y2; alternate parts U7 -> CMP-0094066-1, D10 -> CMP-0002894-2, D11 -> CMP-0002894-2, D12 -> CMP-0002893-1
003: not fitted A1 A2 A3 A4 C1 C2 C3 C4 C5 C6 C41 C44 C45 C46 C72 C73 J1 J2 J3 J22 J24 R1 R2 R3 R6 R7 R9 R10 R11 R12 R14 R15 R17 R18 R21 R22 R23 R24 R25 R26 R27 R30 R32 R33 R34 R54 R69 R70 R71 R73 R74 R99 R100 R101 R103 R108 TP13 TP15 TP16 TP37 TP38 TP39 TP40 TP41 TP42 TP43 TP44 TP45 TP46 U4 U5 Y2; alternate parts U7 -> CMP-0094067-2
004: not fitted A1 A2 A3 A4 C1 C2 C3 C4 C5 C6 C41 C44 C45 C46 C72 C73 J1 J2 J3 J22 J24 R1 R2 R3 R6 R7 R9 R10 R11 R12 R14 R15 R17 R18 R21 R22 R23 R24 R25 R26 R27 R30 R32 R33 R34 R54 R69 R70 R71 R73 R74 R88 R99 R100 R102 R103 R107 TP13 TP15 TP16 TP37 TP38 TP39 TP40 TP41 TP42 TP43 TP44 TP45 TP46 U4 U5 Y2; alternate parts U7 -> CMP-0094068-2
005: not fitted A1 A2 A3 A4 C1 C2 C3 C4 C5 C6 C41 C44 C45 C46 C72 C73 J1 J2 J3 J22 J24 R1 R2 R3 R6 R7 R9 R10 R11 R12 R14 R15 R17 R18 R21 R22 R23 R24 R25 R26 R27 R30 R32 R33 R34 R54 R69 R70 R71 R73 R74 R99 R101 R103 R106 R108 TP13 TP15 TP16 TP37 TP38 TP39 TP40 TP41 TP42 TP43 TP44 TP45 TP46 U4 U5 Y2; alternate parts U7 -> CMP-0094063-2
006: not fitted A1 A2 A3 A4 C1 C2 C3 C4 C5 C6 C41 C44 C45 C46 C72 C73 J1 J2 J3 J16 J19 J20 J22 J24 R1 R3 R6 R7 R9 R10 R11 R12 R14 R15 R17 R18 R21 R22 R23 R24 R25 R26 R27 R30 R32 R33 R34 R54 R69 R70 R71 R73 R74 R79 R82 R84 R87 R99 R102 R103 R106 R107 TP13 TP15 TP16 TP37 TP38 TP39 TP40 TP41 TP42 TP43 TP44 TP45 TP46 U4 U5 Y2; alternate parts U7 -> CMP-0094065-2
